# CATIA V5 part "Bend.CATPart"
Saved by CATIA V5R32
Part number: Bend
Bounding box of the stored display mesh (mm): x -50 to 50, y -150 to 15, z -50 to 115
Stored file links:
  D:\PROJECTS\Project 2022\CATIA V5 6R 2022\Resources\Part Files\c12_catia_v5_6r2022_prt\c12_catia_v5-6r2022 figr_12-39\Bend.CATPart
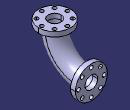
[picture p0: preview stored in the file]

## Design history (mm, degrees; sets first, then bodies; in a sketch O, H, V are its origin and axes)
Body1 (main body)
  Sketch1 on yz-plane, origin (0, 0, 0), H (0, 1, 0), V (0, 0, 1)
    arc A1 centre (0, 100) radius 100 from (-100, 100) to (0, 0) ccw
    point P1 (0, 100)
    coincidence: P1 V
  Sketch2 on zx-plane, origin (0, 0, 0), H (-1, 0, 0), V (0, 0, 1)
    circle A1 centre (0, 0) radius 30
    point P1 (0, -30)
    radius A1 = 30
    coincidence: A1 P1, P1 V
  Rib1: profile Sketch2, centre curve Sketch1
  Sketch3 on face of Rib1, origin (0, 0, 0), H (-1, 0, 0), V (0, 0, 1)
    circle A1 centre (0, 0) radius 50
    point P1 (0, -50)
    radius A1 = 50
    coincidence: A1 P1, P1 V
  Pad1: profile Sketch3, direction (0, 1, 0), length 15
  Sketch4 on face of Rib1, origin (0, 0, 100), H (1, 0, 0), V (0, 1, 0)
    circle A1 centre (0, -100) radius 50
    point P1 (0, -100)
    reference projected circle E1 centre (0, -100) radius 30 from edge [face of Rib1 | face of Rib1]
    radius A1 = 50
    coincidence: P1 V
    concentricity: A1 E1
  Pad2: profile Sketch4, direction (0, 0, 1), length 15
  Sketch5 on face of Pad1, origin (0, 15, 0), H (-1, 0, 0), V (0, 0, 1)
    circle A1 centre (0, 0) radius 20
    radius A1 = 20
  Sketch6 on yz-plane, origin (0, 0, 0), H (0, 1, 0), V (0, 0, 1)
    projected arc E1 centre (0, 100) radius 100 from (-100, 100) to (0, 0) ccw from edge of Sketch1
    line L1 (-100, 100) -> (-100, 115)
    point P3 (-100, 115)
    line L2 (0, 0) -> (15, 0)
    point P4 (15, 0)
    reference projected line E2 (15, 50) -> (15, -50) from edge [face of Pad1 | face of Pad1]
    reference projected line E3 (-50, 115) -> (-150, 115) from edge [face of Pad2 | face of Pad2]
    tangency: L1 E1, L2 E1
    coincidence: P4 E2, P3 E3
  Slot1: profile Sketch5, centre curve Sketch6
  Sketch7 on face of Pad1, origin (0, 15, 0), H (-1, 0, 0), V (0, 0, 1)
    circle A1 centre (0, -40) radius 6
    point P1 (0, -40)
    radius A1 = 6
    distance H P1 = 40
    coincidence: P1 V
  Pocket1: profile Sketch7, direction (0, -1, 0), length 15
  CircPattern1: of Pocket1, instances 8, angular step 45, axis from face of Pad1
  Sketch8 on face of Pad2, origin (0, 0, 115), H (1, 0, 0), V (0, 1, 0)
    circle A1 centre (0, -140) radius 6
    point P1 (0, -140)
    reference projected point E1 (0, -100) from vertex of Sketch1
    radius A1 = 6
    distance E1 P1 = 40
    coincidence: P1 V
  Pocket2: profile Sketch8, direction (0, 0, -1), length 15
  CircPattern2: of Pocket2, instances 8, angular step 45, axis from face of Pad2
